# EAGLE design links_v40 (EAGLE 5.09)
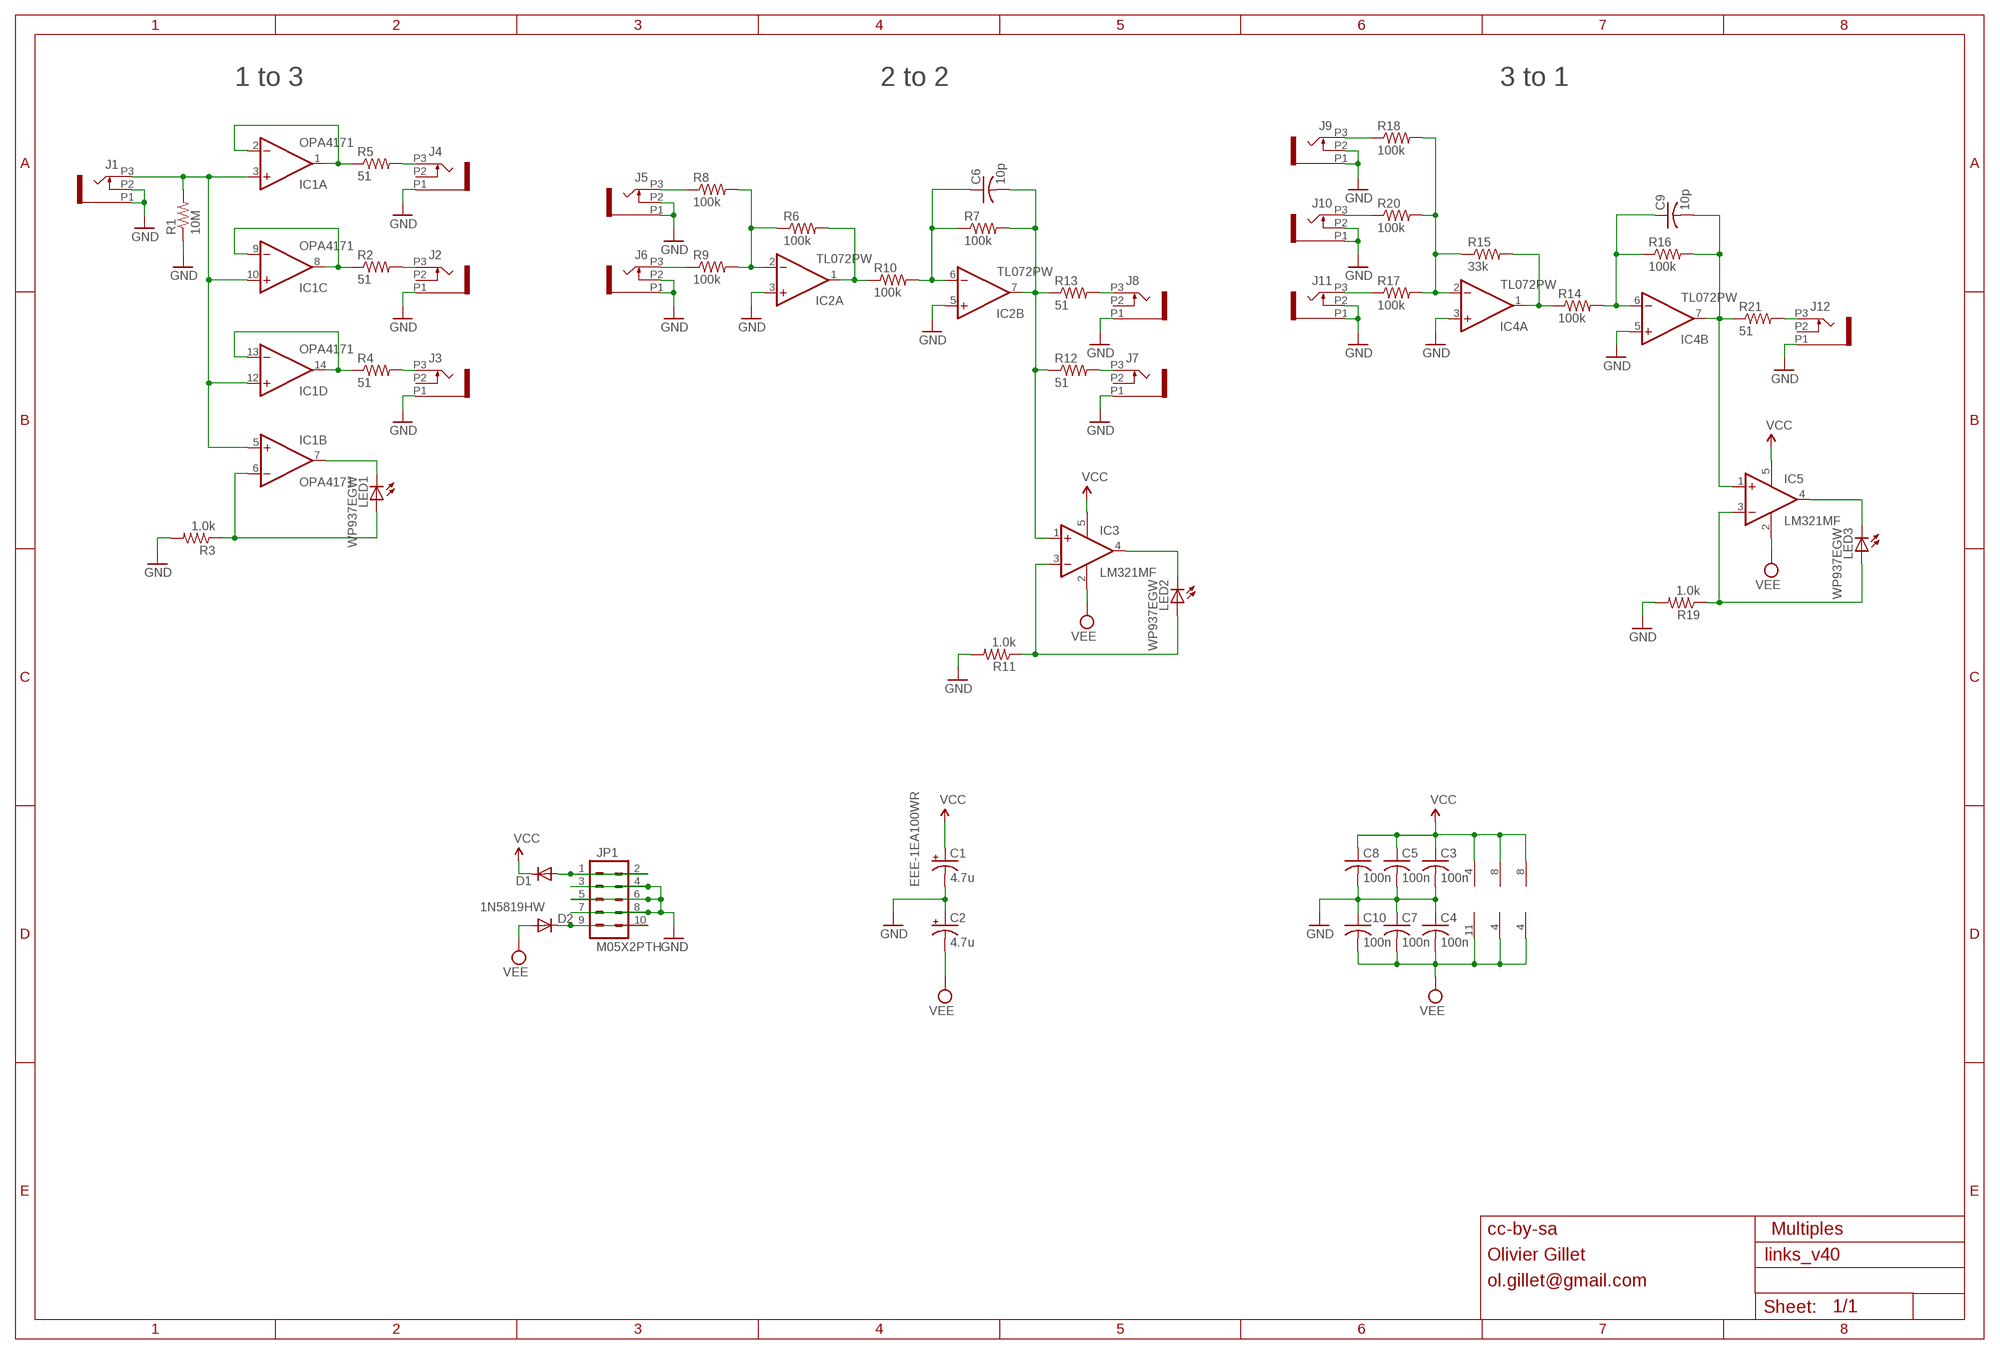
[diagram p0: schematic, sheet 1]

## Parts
C1  4.7u  CPOL-USA  [PANASONIC_A]
C2  4.7u  CPOL-USA  [PANASONIC_A]
C3  100n  C-USC0603  [C0603]
C4  100n  C-USC0603  [C0603]
C5  100n  C-USC0603  [C0603]
C6  10p  C-USC0603  [C0603]
C7  100n  C-USC0603  [C0603]
C8  100n  C-USC0603  [C0603]
C9  10p  C-USC0603  [C0603]
C10  100n  C-USC0603  [C0603]
D1  1N5819HW  DIODE-SOD123  [SOD123]
D2  1N5819HW  DIODE-SOD123  [SOD123]
IC1  OPA4171  TL074PW  [TSSOP14]
IC2  TL072PW  [TSSOP8]
IC3  LM321MF  [SOT23-5]
IC4  TL072PW  [TSSOP8]
IC5  LM321MF  [SOT23-5]
J1  PJ301_THONKICONN6  [WQP_PJ_301M6]
J2  PJ301_THONKICONN6  [WQP_PJ_301M6]
J3  PJ301_THONKICONN6  [WQP_PJ_301M6]
J4  PJ301_THONKICONN6  [WQP_PJ_301M6]
J5  PJ301_THONKICONN6  [WQP_PJ_301M6]
J6  PJ301_THONKICONN6  [WQP_PJ_301M6]
J7  PJ301_THONKICONN6  [WQP_PJ_301M6]
J8  PJ301_THONKICONN6  [WQP_PJ_301M6]
J9  PJ301_THONKICONN6  [WQP_PJ_301M6]
J10  PJ301_THONKICONN6  [WQP_PJ_301M6]
J11  PJ301_THONKICONN6  [WQP_PJ_301M6]
J12  PJ301_THONKICONN6  [WQP_PJ_301M6]
JP1  M05X2PTH  [AVR_ICSP]
LED1  WP937EGW  LED3MM  [LED3MM]
LED2  WP937EGW  LED3MM  [LED3MM]
LED3  WP937EGW  LED3MM  [LED3MM]
R1  10M  R-US_R0603  [R0603]
R2  51  R-US_R0603  [R0603]
R3  1.0k  R-US_R0603  [R0603]
R4  51  R-US_R0603  [R0603]
R5  51  R-US_R0603  [R0603]
R6  100k  R-US_R0603  [R0603]
R7  100k  R-US_R0603  [R0603]
R8  100k  R-US_R0603  [R0603]
R9  100k  R-US_R0603  [R0603]
R10  100k  R-US_R0603  [R0603]
R11  1.0k  R-US_R0603  [R0603]
R12  51  R-US_R0603  [R0603]
R13  51  R-US_R0603  [R0603]
R14  100k  R-US_R0603  [R0603]
R15  33k  R-US_R0603  [R0603]
R16  100k  R-US_R0603  [R0603]
R17  100k  R-US_R0603  [R0603]
R18  100k  R-US_R0603  [R0603]
R19  1.0k  R-US_R0603  [R0603]
R20  100k  R-US_R0603  [R0603]
R21  51  R-US_R0603  [R0603]

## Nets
GND: C1.- C2.+ C3.2 C4.1 C5.2 C7.1 C8.2 C10.1 IC2.3(A:+IN) IC2.5(B:+IN) IC4.3(A:+IN) IC4.5(B:+IN) J1.P1 J1.P2 J2.P1 J3.P1 J4.P1 J5.P1 J5.P2 J6.P1 J6.P2 J7.P1 J8.P1 J9.P1 J9.P2 J10.P1 J10.P2 J11.P1 J11.P2 J12.P1 JP1.3 JP1.4 JP1.5 JP1.6 JP1.7 JP1.8 R1.1 R3.2 R11.2 R19.2
N$1: IC2.1(A:OUT) R6.2 R10.1
N$2: J11.P3 R17.1
N$3: IC1.1(A:OUT) IC1.2(A:-IN) R5.1
N$4: IC1.8(C:OUT) IC1.9(C:-IN) R2.1
N$5: IC1.13(D:-IN) IC1.14(D:OUT) R4.1
N$6: D1.A JP1.1 JP1.2
N$7: IC1.3(A:+IN) IC1.5(B:+IN) IC1.10(C:+IN) IC1.12(D:+IN) J1.P3 R1.2
N$8: IC1.7(B:OUT) LED1.K(C)
N$9: J10.P3 R20.1
N$10: J6.P3 R9.1
N$11: J4.P3 R5.2
N$12: J2.P3 R2.2
N$13: J3.P3 R4.2
N$14: IC3.4(OUT) LED2.K(C)
N$15: J5.P3 R8.1
N$16: J7.P3 R12.2
N$17: J8.P3 R13.2
N$18: C9.2 IC4.7(B:OUT) IC5.1(+IN) R16.2 R21.1
N$19: IC5.3(-IN) LED3.A R19.1
N$20: D2.C JP1.9 JP1.10
N$21: IC1.6(B:-IN) LED1.A R3.1
N$22: J9.P3 R18.1
N$23: J12.P3 R21.2
N$24: IC4.2(A:-IN) R15.1 R17.2 R18.2 R20.2
N$25: IC4.1(A:OUT) R14.1 R15.2
N$26: C6.2 IC2.7(B:OUT) IC3.1(+IN) R7.2 R12.1 R13.1
N$27: C9.1 IC4.6(B:-IN) R14.2 R16.1
N$29: IC3.3(-IN) LED2.A R11.1
N$30: IC5.4(OUT) LED3.K(C)
N$31: IC2.2(A:-IN) R6.1 R8.2 R9.2
N$32: C6.1 IC2.6(B:-IN) R7.1 R10.2
VCC: C1.+ C3.1 C5.1 C8.1 D1.C IC1.4(P:V+) IC2.8(P:V+) IC3.5(V+) IC4.8(P:V+) IC5.5(V+)
VEE: C2.- C4.2 C7.2 C10.2 D2.A IC1.11(P:V-) IC2.4(P:V-) IC3.2(V-) IC4.4(P:V-) IC5.2(V-)
Unconnected: J2.P2 J3.P2 J4.P2 J7.P2 J8.P2 J12.P2

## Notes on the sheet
- 1 to 3 | 2 to 2 | 3 to 1
- EEE-1EA100WR
- cc-by-sa | Multiples
- Olivier Gillet
- ol.gillet@gmail.com

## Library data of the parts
C1 C2 = rcl:CPOL-US: POLARIZED CAPACITOR, American symbol
C3-C10 = rcl:C-US: CAPACITOR, American symbol
D1 D2 = diode:DIODE-: DIODE
IC1 = linear:TL074: OP AMP
IC2 IC4 = linear:TL072: OP AMP
IC3 IC5 = linear:LM321?*: Low Power Single Op Amp Source: http://cache.national.com/ds/LM/LM321.pdf
J1-J12 = og-pj301:PJ301_THONKICONN
JP1 = og-header:M05X2: Header 5x2 Standard 10-pin dual row 0.1" header. Commonly used with AVR-ISP. Use with Spark Fun Electronics SKU: PRT-00778
LED1-LED3 = led:LED: LED
R1-R21 = rcl:R-US_: RESISTOR, American symbol

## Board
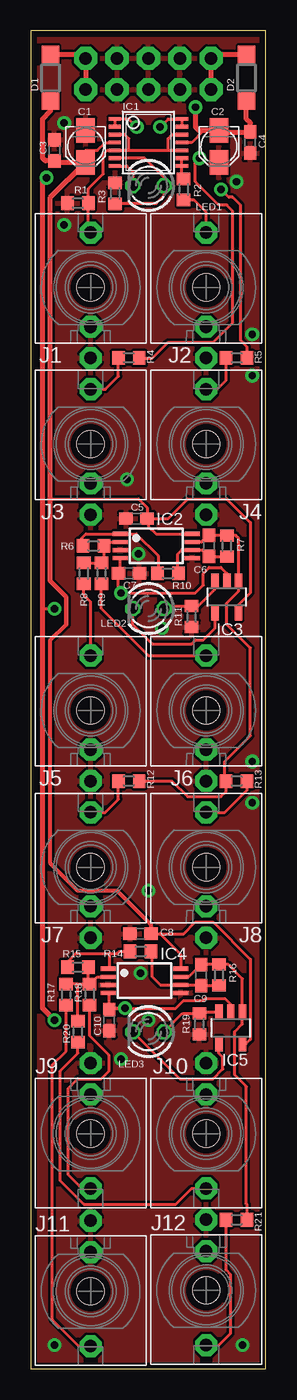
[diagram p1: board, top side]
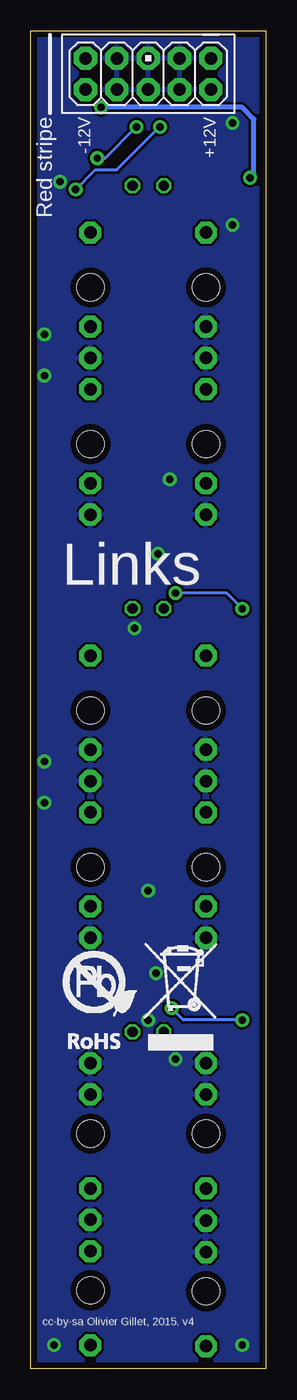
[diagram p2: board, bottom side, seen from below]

Size 19.03 x 108.43 mm. Coordinates in mm from the lower left corner, seen from the top.
Outline: 0,0 19.03,0 19.03,108.43 0,108.43 0,0
Copper layers (1*16): Top 0.035mm / dielectric 1.5mm / Bottom 0.035mm
Design rules "PCBCart-Standard *": minimum track width 8mil, minimum drill 0.4mm, track to track 8mil, track to pad 8mil, pad to pad 8mil, via to via 8mil, smd to smd 8mil, copper to edge 20mil, drill to drill 8mil, minimum pad ring 8mil, minimum via ring 10mil, stop-mask expansion 3mil, vias tented up to drill 25mil, thermal gap 8mil

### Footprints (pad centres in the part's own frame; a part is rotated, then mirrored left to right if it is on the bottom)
PANASONIC_A = smd 2 x 1.5: + 1.3,0; - -1.3,0
C0603 = smd 1.1 x 1: 1 -0.85,0; 2 0.85,0
SOD123 = smd 1.4 x 1.4: A 1.9,0; C -1.9,0
TSSOP14 = smd 0.305 x 0.991: 1 -1.905,-2.718; 2 -1.27,-2.718; 3 -0.635,-2.718; 4 0,-2.718; 5 0.635,-2.718; 6 1.27,-2.718; 7 1.905,-2.718; 8 1.905,2.718; 9 1.27,2.718; 10 0.635,2.718; 11 0,2.718; 12 -0.635,2.718; 13 -1.27,2.718; 14 -1.905,2.718
TSSOP8 = smd 0.35 x 1.2: 1 -0.975,-2.925; 2 -0.325,-2.925; 3 0.325,-2.925; 4 0.975,-2.925; 5 0.975,2.925; 6 0.325,2.925; 7 -0.325,2.925; 8 -0.975,2.925
SOT23-5 = smd 0.6 x 1.2: 1 -0.95,-1.306; 2 0,-1.306; 3 0.95,-1.306; 4 0.95,1.306; 5 -0.95,1.306
WQP_PJ_301M6 = drill 1.016 pad 1.778 octagon: P1 0,-5.715; P2 0,-3.175; P3 0,4.445 | hole 2.2: 0,0
AVR_ICSP = drill 1.016 pad 1.88 octagon: 1 -1.27,5.08; 2 1.27,5.08; 3 -1.27,2.54; 4 1.27,2.54; 5 -1.27,0; 6 1.27,0; 7 -1.27,-2.54; 8 1.27,-2.54; 9 -1.27,-5.08; 10 1.27,-5.08
LED3MM = drill 0.813 octagon: A -1.27,0; K 1.27,0
R0603 = smd 1 x 1.1: 1 -0.85,0; 2 0.85,0

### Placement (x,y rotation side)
C1  4.45,99.06 270 top
C2  15.24,99.06 270 top
C3  1.91,98.74 90 top
C4  17.78,99.38 90 top
C5  8.57,68.9 180 top
C6  14.45,66.67 90 top
C7  7.94,64.45 180 top
C8  8.89,35.24 180 top
C9  13.81,31.91 90 top
C10  6.35,28.26 90 top
D1  1.59,104.62 90 top
D2  17.46,104.62 270 top
IC1  9.53,99.38 270 top
IC2  10.16,66.67 270 top
IC3  15.88,62.55 180 top
IC4  9.21,31.43 270 top
IC5  16.19,27.62 180 top
J1  4.84,87.63 0 top
J2  14.21,87.63 0 top
J3  4.84,74.93 0 top
J4  14.21,74.93 0 top
J5  4.84,53.34 0 top
J6  14.21,53.34 0 top
J7  4.84,40.64 0 top
J8  14.21,40.64 0 top
J9  4.84,19.05 180 top
J10  14.21,19.05 180 top
J11  4.84,6.27 180 top
J12  14.21,6.35 180 top
JP1  9.53,104.93 270 bottom
LED1  9.53,95.89 180 top
LED2  9.53,61.59 180 top
LED3  9.53,27.3 180 top
R1  3.81,94.46 0 top
R2  12.38,95.57 270 top
R3  6.83,95.25 90 top
R4  7.94,81.92 180 top
R5  16.67,81.92 180 top
R6  5.08,66.67 180 top
R7  15.88,66.67 90 top
R8  4.29,64.45 90 top
R9  5.71,64.45 90 top
R10  11.11,64.45 0 top
R11  13.02,60.96 270 top
R12  7.94,47.62 180 top
R13  16.67,47.62 0 top
R14  8.89,33.81 0 top
R15  3.81,32.54 180 top
R16  15.24,31.91 90 top
R17  2.86,30.32 90 top
R18  4.76,30.32 90 top
R19  13.65,27.94 270 top
R20  3.81,27.3 90 top
R21  16.67,12.06 180 top
U$2  [ROHS]  17.3,25.24 0 bottom

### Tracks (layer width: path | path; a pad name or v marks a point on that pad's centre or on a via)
GND  (via drill 0.6)
  other vias: 8.73,66.04 7.78,72.07 8.89,32.07 7.3,25.08 9.53,28.26 9.53,38.73 2.7,92.71 10.64,60.01 1.91,1.91 17.14,1.91 2.7,100.97 16.67,96.2 17.94,80.49 17.94,83.82 17.94,45.88 17.94,49.21
  pour Bottom: 0,108.43 0,0 19.05,0 19.05,108.43
  pour Top: 0,108.43 0,0 19.05,0 19.05,108.43
N$1
  Top 0.254: R10.1 10.32,64.51 10.32,65.88 8.55,67.65 7.94,67.65 IC2.1 4.47,67.65 4.13,67.31 4.13,67.21 4.45,66.89 R6.2
N$2
  Top 0.254: R17.1 2.86,25.72 1.75,24.61 1.75,3.97 3.89,1.83 J11.P3
N$3  (via drill 0.6)
  Top 0.254: IC1.2 IC1.1 7.94,101.28 v8.57,100.65 | v15.4,95.57 16.03,94.93 16.35,94.93 16.99,94.3 16.99,83.34 17.52,82.81 R5.1
  Bottom 0.254: v15.4,95.57 13.81,97.16 12.06,97.16 v8.57,100.65
N$4
  Top 0.254: IC1.9 IC1.8 12.24,96.56 R2.1
N$5  (via drill 0.6)
  Top 0.254: IC1.13 IC1.14 11.11,101.28 v10.48,100.65 | v13.65,98.11 13.34,97.79 13.34,96.2 15.24,94.3 15.88,94.3 16.35,93.82 16.35,84.77 14.76,83.19 11.11,83.19 9.84,81.92 R4.1
  Bottom 0.254: v13.65,98.11 13.02,98.11 v10.48,100.65
N$6
  Top 0.406: JP1.2 JP1.1 4.13,106.52 D1.A
N$7
  Top 0.254: 7.94,98.74 IC1.5 6.19,98.74 5.87,98.42 5.87,96.84 4.66,95.62 R1.2 4.66,92.26 J1.P3 | 7.94,98.74 11.11,98.74 | 11.11,98.74 IC1.10 | IC1.3 7.62,100.01 7.94,99.69 7.94,98.74 | IC1.12 11.43,100.01 11.11,99.69 11.11,98.74
N$8
  Top 0.254: LED1.K 8.26,97 7.78,97.47 IC1.7
N$9
  Top 0.254: R20.1 3.81,25.56 2.38,24.13 2.38,15.24 4.29,13.34 11.75,13.34 13.02,14.61 J10.P3
N$10
  Top 0.254: J6.P3 9.53,57.78 5.71,61.59 R9.1
N$11
  Top 0.254: J4.P3 15.08,79.38 15.82,80.11 R5.2
N$12
  Top 0.254: R2.2 13.23,94.72 14.21,93.74 J2.P3
N$13
  Top 0.254: J3.P3 6.03,79.38 7.09,80.43 R4.2
N$14
  Top 0.254: LED2.K 8.26,60.33 9.84,58.74 13.02,58.74 13.34,59.05 13.97,59.05 14.93,60.01 IC3.4
N$15
  Top 0.254: R8.1 4.29,62.71 4.84,62.15 J5.P3
N$16
  Top 0.254: J7.P3 6.03,45.09 7.09,46.14 R12.2
N$17
  Top 0.254: J8.P3 15.72,45.09 17.52,46.89 R13.2
N$18
  Top 0.254: IC4.7 12.81,31.76 C9.2 R16.2 15.98,32.76 17.14,31.59 IC5.1 17.14,27.94 16.51,27.3 16.51,23.81 17.46,22.86 17.46,13.34 17.52,13.28 R21.1
N$19
  Top 0.254: LED3.A 12.28,28.79 R19.1 13.79,28.93 IC5.3 15.06,29.11
N$20
  Top 0.406: JP1.10 JP1.9 14.92,106.52 D2.C
N$21
  Top 0.254: IC1.6 9.21,98.11 10.79,96.52 LED1.A 10.79,95.09 10.16,94.46 6.88,94.46 R3.1
N$22
  Top 0.254: J9.P3 4.13,14.61 3.02,15.72 3.02,22.7 3.81,23.5 5.71,23.5 6.35,24.13 6.35,25.4 4.76,26.99 R18.1
N$23
  Top 0.254: J12.P3 15.24,1.91 16.19,2.86 16.19,7.62 15.82,7.99 R21.2
N$24
  Top 0.254: R20.2 3.81,31.17 | R18.2 5.03,31.44 | 3.81,31.17 | 3.81,31.17 R17.2 | 3.81,31.17 R18.2 | R18.2 4.66,31.27 R15.1 | IC4.2 5.4,31.75 4.82,31.17 R18.2
N$25
  Top 0.254: R15.2 3.02,32.6 3.02,33.02 3.65,33.66 6.35,33.66 | 6.35,33.66 6.99,33.66 7.14,33.81 R14.1 | IC4.1 6.35,32.48 6.35,33.66
N$26
  Top 0.254: IC2.7 13.81,67 13.81,66.99 14.34,67.53 C6.2 R7.2 16.61,67.53 16.82,67.31 IC3.1 16.86,63.82 16.83,63.78 16.83,63.02 15.88,62.07 15.88,60.33 17.78,58.42 17.78,51.28 15.72,49.21 15.72,47.73 R13.1 15.82,46.77 15.4,46.35 12.7,46.35 11.43,47.62 R12.1
N$27
  Top 0.254: R14.2 9.84,33.71 9.84,31.75 10.48,31.11 IC4.6 13.76,31.11 C9.1 R16.1
N$29
  Top 0.254: IC3.3 14.93,63.19 13.55,61.81 R11.1 11.01,61.81 LED2.A
N$30
  Top 0.254: 15.21,26.35 IC5.4 15.24,25.56 15.56,25.24 15.56,24.29 14.76,23.5 12.06,23.5 LED3.K
N$31
  Top 0.254: R8.2 R9.2 5.93,65.52 R6.1 | R6.1 5.94,66.68 | R6.1 6.25,67 IC2.2
N$32
  Top 0.254: R7.1 C6.1 13.92,66.35 IC2.6 12.22,66.35 11.91,66.04 11.91,64.51 R10.2
VCC
  Top 0.254: IC2.8 13.06,67.63 10.16,67.63 9.53,68.26 9.53,68.8 C5.1 | 9.63,35.24 C8.1 10.48,35.24 | IC4.8 12.13,33.59 10.48,35.24 | 1.59,70.48 8.73,70.48 9.42,69.79 C5.1 | 10.48,35.24 12.38,35.24 13.34,36.2 14.76,36.2 17.78,33.18 17.78,26.67 17.43,26.32 IC5.5 | IC3.5 16.83,61.91 17.78,62.87 17.78,68.58 15.88,70.48 12.7,70.48 11.11,68.9 C5.1 | IC1.4 6.03,99.38 5.4,98.74 4.45,98.74 C1.+
  Top 0.305: 1.59,59.05 1.59,40.96 3.81,38.73 6.99,38.73 9.74,35.98 C8.1
  Top 0.33: 1.59,59.05 2.86,60.33
  Top 0.356: 2.86,60.33 2.86,62.55
  Top 0.381: 2.86,62.55 1.59,63.82
  Top 0.406: 1.59,63.82 1.59,70.48 1.59,94.93 4.42,97.76 C1.+ 2.04,97.76 C3.1 1.17,97.89 0.95,98.11 0.95,101.28 1.59,101.92 D1.C
VEE  (via drill 0.6)
  Top 0.254: C7.2 7.24,64.6 IC2.4 | C7.2 6.77,64.14 | C7.2 7.09,63.08 v7.3,62.87 13.34,62.87 13.97,63.5 13.97,64.45 14.45,64.93 15.4,64.93 15.88,64.45 IC3.2 | IC4.4 6.35,30.39 C10.2 | C10.2 6.25,29.21 v7.62,29.21 | C10.2 6.45,29.21 11.75,29.21 12.38,29.84 13.97,29.84 14.13,30 15.72,30 16.19,29.53 IC5.2 | 0.95,61.59 v1.91,61.59 | IC1.11 13.02,99.38 14,100.36 C2.-
  Top 0.406: v1.91,28.26 0.95,29.21 0.95,61.59 0.95,96.2 v1.27,96.52 | 16.98,102.23 D2.A 17.46,101.28 17.78,100.97 C4.2 15.37,100.23 C2.- 13.62,100.36 13.34,100.65 v13.34,102.23
  Bottom 0.254: v7.3,62.87 3.17,62.87 v1.91,61.59 | v1.91,28.26 6.67,28.26 v7.62,29.21
  Bottom 0.406: v13.34,102.23 1.91,102.23 0.95,101.28 0.95,96.84 v1.27,96.52

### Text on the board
bPlace: Red stripe
bNames: +12V | -12V | Links | cc-by-sa Olivier Gillet, 2015. v4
